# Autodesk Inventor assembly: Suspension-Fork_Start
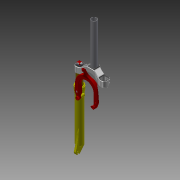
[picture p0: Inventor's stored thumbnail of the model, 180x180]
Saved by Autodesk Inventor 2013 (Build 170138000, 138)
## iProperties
Shininess: 64.0
Length Units: 11272
Angle Units: 11279
Time Units: 11290
Mass Units: 11286
Length Display Precision: 3
Angle Display Precision: 2
Compacted: True
Created: 2001-11
Part Number: Suspension-Fork_Start
Document SubType Name: Assembly
Designer: Autodesk, Inc.
Mass: 432.707 g
Surface Area: 2527.99 cm^2
Volume: 429.637 cm^3
Density: 1.00715 g/cm^3
Density: 0.0
Volumn: 0.0
Area: 0.0
PropertySet Name: Model Information
Control State: 0
Master: False
Checked Out: False
Author: Autodesk, Inc.
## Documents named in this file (11)
- C:\Users\boganb\Documents\B2 Design\Goodyear\2013 Tutorial Files\Assembly FEA 3\Suspension-Fork_Start.iam
- C:\Users\boganb\Documents\B2 Design\Goodyear\2013 Tutorial Files\Assembly FEA 3\Components\Dial-Elastomer.iam
- C:\Users\boganb\Documents\B2 Design\Goodyear\2013 Tutorial Files\Assembly FEA 3\Components\Head Tube.ipt
- C:\Users\boganb\Documents\B2 Design\Goodyear\2013 Tutorial Files\Assembly FEA 3\Components\Fork-Slider.ipt
- C:\Users\boganb\Documents\B2 Design\Goodyear\2013 Tutorial Files\Assembly FEA 3\Components\Fork-Piston.ipt
- C:\Users\boganb\Documents\B2 Design\Goodyear\2013 Tutorial Files\Assembly FEA 3\Components\Fork-Crown.ipt
- C:\Users\boganb\Documents\B2 Design\Goodyear\2013 Tutorial Files\Assembly FEA 3\Components\Fork-Brace.ipt
- C:\Users\boganb\Documents\B2 Design\Goodyear\2013 Tutorial Files\Assembly FEA 3\Components\Fork-Tube.ipt
- C:\Users\boganb\Documents\B2 Design\Goodyear\2013 Tutorial Files\Assembly FEA 3\Components\Fork-Damper.ipt
- C:\Users\boganb\Documents\B2 Design\Goodyear\2013 Tutorial Files\Assembly FEA 3\Standard Parts\UNI 5933 - M4 x 12.ipt
- C:\Users\boganb\Documents\B2 Design\Goodyear\2013 Tutorial Files\Assembly FEA 3\Standard Parts\NF E 25-125 - M3 x 10.ipt
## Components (11 placed, 10 different names)
1. Fork-Crown:1 — Mate:7, Tangent:1, Angle:1, Mate:10, Insert:15, Mate:11, Insert:20, Insert:21
2. Head Tube:1 — Mate:7, Tangent:1
3. Fork-Brace:1 — Insert:22
4. Dial-Elastomer [sub-assembly] — Insert:19
5. Fork-Slider:1 — Insert:2, Angle:1, Mate:10, Mate:11
6. Fork-Piston:1 — Insert:2
7. UNI 5933 M4 x 12:1 — Insert:22
8. NF E 25-125 M3 x 10:1 — Insert:20
9. NF E 25-125 M3 x 10:2 — Insert:21
10. Fork-Tube:1 — Insert:15, Insert:16, Insert:19
11. Fork-Damper:1 — Insert:16
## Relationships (12: Insert 7, Mate 3, Tangent 1, Angle 1)
- Insert:2: Fork-Slider:1 ↔ Fork-Piston:1
- Mate:7: Fork-Crown:1 ↔ Head Tube:1
- Tangent:1: Fork-Crown:1 ↔ Head Tube:1
- Angle:1: Fork-Crown:1 ↔ Fork-Slider:1
- Mate:10: Fork-Crown:1 ↔ Fork-Slider:1
- Insert:15: Fork-Crown:1 ↔ Fork-Tube:1
- Insert:16: Fork-Tube:1 ↔ Fork-Damper:1
- Mate:11: Fork-Crown:1 ↔ Fork-Slider:1
- Insert:19: Dial-Elastomer ↔ Fork-Tube:1
- Insert:20: Fork-Crown:1 ↔ NF E 25-125 M3 x 10:1
- Insert:21: Fork-Crown:1 ↔ NF E 25-125 M3 x 10:2
- Insert:22: Fork-Brace:1 ↔ UNI 5933 M4 x 12:1
